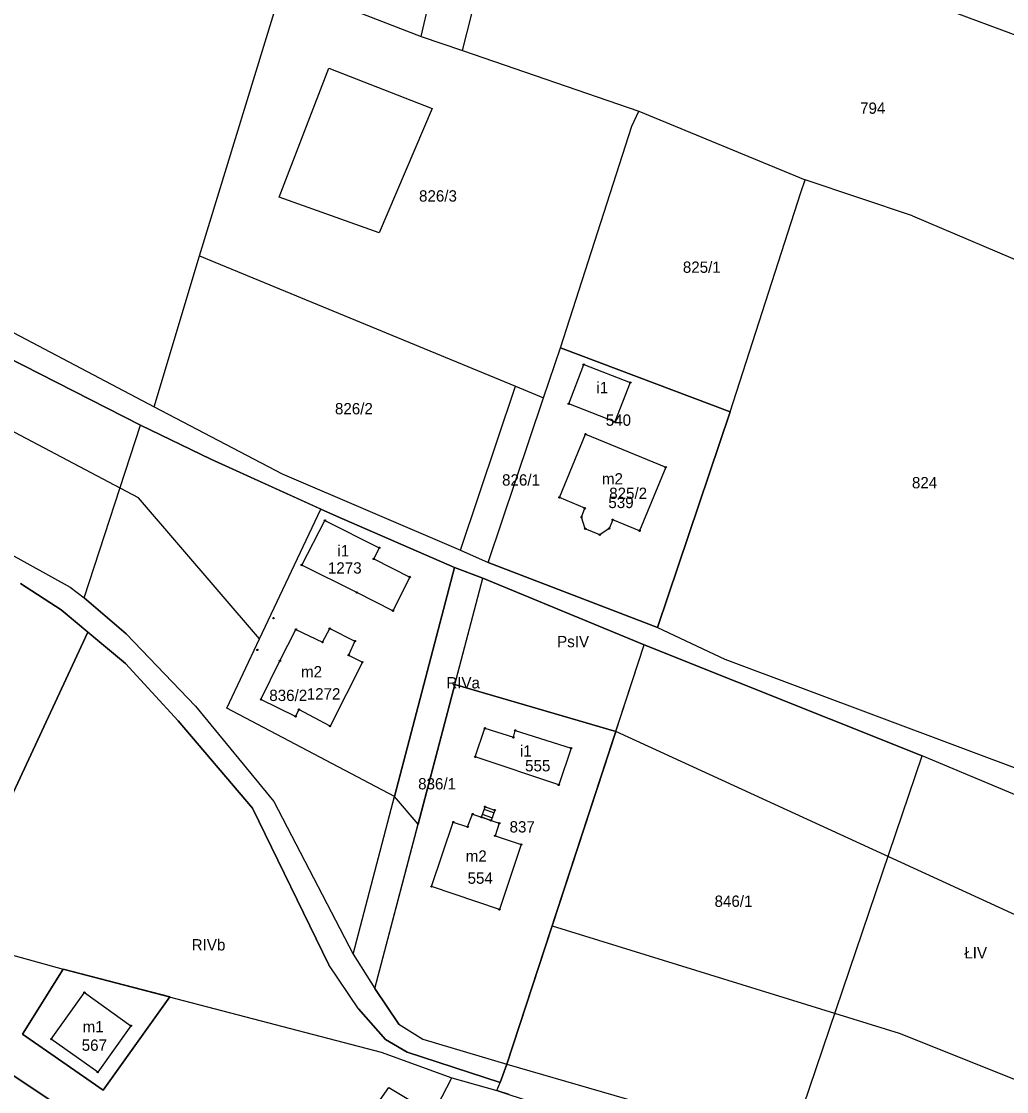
# Model space of a CAD drawing. Extents: x 7498273 to 7499989, y 5499795 to 5500810.
# Drawn here: x 7499281.1 to 7499411.6, y 5500351 to 5500492.7 of the extents above; entities that cross this region are included whole.
import ezdxf

# ---------------------------------------------------------------- set-up
doc = ezdxf.new("R2010")
doc.units = 0
for name, color, linetype in [('209-oznaczenie konturu klasyfikacyjnego', 7, 'Continuous'), ('211-numer działki ewidencyjnej', 7, 'Continuous'), ('217-kontur klasyfikacyjny', 7, 'Continuous'), ('218-kontur użytku gruntowego', 7, 'Continuous'), ('219-działka ewidencyjna', 7, 'Continuous'), ('312-budynek ewidencyjny', 7, 'Continuous'), ('312-oznaczenie budynku ewidencyjnego', 7, 'Continuous'), ('312-oznaczenie budynku ewidencyjnego-Atr117', 7, 'Continuous'), ('352-schody', 7, 'Continuous'), ('Punkt budynku', 7, 'Continuous')]:
    doc.layers.add(name, color=color, linetype=linetype)

# ---------------------------------------------------------------- blocks, each defined once
blk = doc.blocks.new('PUNKTBUD')
blk.add_circle((0, 0), 0.09)

msp = doc.modelspace()

# ---------------------------------------------------------------- linework, layer by layer
at = {"layer": '217-kontur klasyfikacyjny'}
for points in [[(7499296.61, 5500429.63), (7499178.7, 5500491.9)], [(7499315.23, 5500469.46), (7499321.8, 5500486.55)], [(7499321.8, 5500486.55), (7499335.49, 5500481.22)], [(7499335.49, 5500481.22), (7499328.47, 5500464.71)], [(7499328.47, 5500464.71), (7499315.23, 5500469.46)], [(7499254.08, 5500465.15), (7499298.69, 5500441.68)], [(7499219.39, 5500455.52), (7499287.55, 5500417.77)], [(7499296.87, 5500439.23), (7499270.17, 5500452.83)], [(7499350.27, 5500442.88), (7499352.51, 5500449.51)], [(7499352.51, 5500449.51), (7499374.97, 5500441.03)], [(7499342.94, 5500421.06), (7499350.27, 5500442.88)], [(7499298.69, 5500441.68), (7499315.65, 5500432.8)], [(7499374.97, 5500441.03), (7499365.34, 5500412.42)], [(7499306.2, 5500434.76), (7499296.87, 5500439.23)], [(7499320.75, 5500428.13), (7499306.2, 5500434.76)], [(7499315.65, 5500432.8), (7499339.26, 5500422.68)], [(7499312.63, 5500410.92), (7499296.61, 5500429.63)], [(7499312.63, 5500410.92), (7499320.75, 5500428.13)], [(7499320.75, 5500428.13), (7499322.82, 5500427.19)], [(7499322.82, 5500427.19), (7499338.47, 5500420.37)], [(7499339.26, 5500422.68), (7499342.94, 5500421.06)], [(7499338.47, 5500420.37), (7499330.52, 5500390.03)], [(7499342.23, 5500418.97), (7499338.47, 5500420.37)], [(7499365.34, 5500412.42), (7499342.94, 5500421.06)], [(7499338.53, 5500404.91), (7499342.23, 5500418.97)], [(7499363.59, 5500410.14), (7499342.23, 5500418.97)], [(7499286.37, 5500414.76), (7499280.96, 5500418.29)], [(7499287.55, 5500417.77), (7499289.39, 5500416.38)], [(7499289.39, 5500416.38), (7499294.97, 5500411.6)], [(7499289.91, 5500411.82), (7499286.37, 5500414.76)], [(7499277.96, 5500386.26), (7499289.91, 5500411.82)], [(7499294.88, 5500407.68), (7499289.91, 5500411.82)], [(7499294.97, 5500411.6), (7499304.17, 5500402.04)], [(7499365.34, 5500412.42), (7499374.26, 5500408.23)], [(7499308.3, 5500401.74), (7499312.63, 5500410.92)], [(7499359.84, 5500398.68), (7499363.59, 5500410.14)], [(7499400.41, 5500395.43), (7499363.59, 5500410.14)], [(7499301.84, 5500400.08), (7499294.88, 5500407.68)], [(7499374.26, 5500408.23), (7499415.1, 5500392.98)], [(7499333.66, 5500386.37), (7499338.53, 5500404.91)], [(7499338.53, 5500404.91), (7499359.84, 5500398.68)], [(7499304.17, 5500402.04), (7499314.54, 5500389.39)], [(7499330.52, 5500390.03), (7499308.3, 5500401.74)], [(7499311.71, 5500388.52), (7499301.84, 5500400.08)], [(7499359.84, 5500398.68), (7499351.41, 5500372.91)], [(7499417.66, 5500372.13), (7499359.84, 5500398.68)], [(7499414.64, 5500389.48), (7499400.41, 5500395.43)], [(7499314.54, 5500389.39), (7499325.06, 5500369.17)], [(7499333.66, 5500386.37), (7499330.52, 5500390.03)], [(7499321.84, 5500367.74), (7499311.71, 5500388.52)], [(7499327.93, 5500364.61), (7499333.66, 5500386.37)], [(7499351.41, 5500372.91), (7499345.42, 5500354.59)], [(7499351.41, 5500372.91), (7499397.37, 5500358.71)], [(7499325.06, 5500369.17), (7499327.93, 5500364.61)], [(7499325.73, 5500361.93), (7499321.84, 5500367.74)], [(7499259.58, 5500366.67), (7499295.09, 5500343.03)], [(7499281.22, 5500358.58), (7499286.62, 5500367.17)], [(7499286.62, 5500367.17), (7499300.74, 5500363.49)], [(7499300.74, 5500363.49), (7499291.91, 5500351.13)], [(7499329.32, 5500357.84), (7499325.73, 5500361.93)], [(7499291.91, 5500351.13), (7499281.22, 5500358.58)], [(7499332.19, 5500356.19), (7499329.32, 5500357.84)], [(7499397.37, 5500358.71), (7499452.93, 5500336.49)], [(7499344.53, 5500352.15), (7499332.19, 5500356.19)], [(7499345.42, 5500354.59), (7499344.53, 5500352.15)], [(7499344.06, 5500351.09), (7499344.53, 5500352.15)], [(7499321.5, 5500339.77), (7499329.78, 5500351.5)], [(7499329.78, 5500351.5), (7499335.63, 5500347.98)], [(7499345.71, 5500350.55), (7499344.06, 5500351.09)]]:
    msp.add_lwpolyline(points, dxfattribs=at)
at = {"layer": '218-kontur użytku gruntowego'}
for points in [[(7499296.61, 5500429.63), (7499178.7, 5500491.9)], [(7499315.23, 5500469.46), (7499321.8, 5500486.55)], [(7499321.8, 5500486.55), (7499335.49, 5500481.22)], [(7499335.49, 5500481.22), (7499328.47, 5500464.71)], [(7499328.47, 5500464.71), (7499315.23, 5500469.46)], [(7499254.08, 5500465.15), (7499298.69, 5500441.68)], [(7499219.39, 5500455.52), (7499287.55, 5500417.77)], [(7499296.87, 5500439.23), (7499270.17, 5500452.83)], [(7499350.27, 5500442.88), (7499352.51, 5500449.51)], [(7499352.51, 5500449.51), (7499374.97, 5500441.03)], [(7499342.94, 5500421.06), (7499350.27, 5500442.88)], [(7499298.69, 5500441.68), (7499315.65, 5500432.8)], [(7499374.97, 5500441.03), (7499365.34, 5500412.42)], [(7499306.2, 5500434.76), (7499296.87, 5500439.23)], [(7499320.75, 5500428.13), (7499306.2, 5500434.76)], [(7499315.65, 5500432.8), (7499339.26, 5500422.68)], [(7499312.63, 5500410.92), (7499296.61, 5500429.63)], [(7499312.63, 5500410.92), (7499320.75, 5500428.13)], [(7499322.82, 5500427.19), (7499320.75, 5500428.13)], [(7499338.47, 5500420.37), (7499322.82, 5500427.19)], [(7499339.26, 5500422.68), (7499342.94, 5500421.06)], [(7499330.52, 5500390.03), (7499338.47, 5500420.37)], [(7499342.23, 5500418.97), (7499338.47, 5500420.37)], [(7499342.94, 5500421.06), (7499365.34, 5500412.42)], [(7499338.53, 5500404.91), (7499342.23, 5500418.97)], [(7499363.59, 5500410.14), (7499342.23, 5500418.97)], [(7499286.37, 5500414.76), (7499280.96, 5500418.29)], [(7499287.55, 5500417.77), (7499289.39, 5500416.38)], [(7499289.39, 5500416.38), (7499294.97, 5500411.6)], [(7499289.91, 5500411.82), (7499286.37, 5500414.76)], [(7499289.91, 5500411.82), (7499277.96, 5500386.26)], [(7499294.88, 5500407.68), (7499289.91, 5500411.82)], [(7499294.97, 5500411.6), (7499304.17, 5500402.04)], [(7499365.34, 5500412.42), (7499374.26, 5500408.23)], [(7499308.3, 5500401.74), (7499312.63, 5500410.92)], [(7499359.84, 5500398.68), (7499363.59, 5500410.14)], [(7499400.41, 5500395.43), (7499363.59, 5500410.14)], [(7499301.84, 5500400.08), (7499294.88, 5500407.68)], [(7499374.26, 5500408.23), (7499415.1, 5500392.98)], [(7499338.53, 5500404.91), (7499333.66, 5500386.37)], [(7499359.84, 5500398.68), (7499338.53, 5500404.91)], [(7499304.17, 5500402.04), (7499314.54, 5500389.39)], [(7499330.52, 5500390.03), (7499308.3, 5500401.74)], [(7499311.71, 5500388.52), (7499301.84, 5500400.08)], [(7499351.41, 5500372.91), (7499359.84, 5500398.68)], [(7499417.66, 5500372.13), (7499359.84, 5500398.68)], [(7499414.64, 5500389.48), (7499400.41, 5500395.43)], [(7499314.54, 5500389.39), (7499325.06, 5500369.17)], [(7499333.66, 5500386.37), (7499330.52, 5500390.03)], [(7499321.84, 5500367.74), (7499311.71, 5500388.52)], [(7499327.93, 5500364.61), (7499333.66, 5500386.37)], [(7499345.42, 5500354.59), (7499351.41, 5500372.91)], [(7499351.41, 5500372.91), (7499397.37, 5500358.71)], [(7499325.06, 5500369.17), (7499327.93, 5500364.61)], [(7499325.73, 5500361.93), (7499321.84, 5500367.74)], [(7499259.58, 5500366.67), (7499295.09, 5500343.03)], [(7499286.62, 5500367.17), (7499281.22, 5500358.58)], [(7499300.74, 5500363.49), (7499286.62, 5500367.17)], [(7499291.91, 5500351.13), (7499300.74, 5500363.49)], [(7499327.93, 5500364.61), (7499331.09, 5500359.88)], [(7499329.32, 5500357.84), (7499325.73, 5500361.93)], [(7499331.09, 5500359.88), (7499334.28, 5500357.9)], [(7499281.22, 5500358.58), (7499291.91, 5500351.13)], [(7499332.19, 5500356.19), (7499329.32, 5500357.84)], [(7499334.28, 5500357.9), (7499345.42, 5500354.59)], [(7499397.37, 5500358.71), (7499452.93, 5500336.49)], [(7499344.53, 5500352.15), (7499332.19, 5500356.19)], [(7499345.42, 5500354.59), (7499344.53, 5500352.15)], [(7499344.06, 5500351.09), (7499344.53, 5500352.15)], [(7499321.5, 5500339.77), (7499329.78, 5500351.5)], [(7499329.78, 5500351.5), (7499335.63, 5500347.98)], [(7499345.71, 5500350.55), (7499344.06, 5500351.09)]]:
    msp.add_lwpolyline(points, dxfattribs=at)
at = {"layer": '219-działka ewidencyjna'}
for points in [[(7499339.53, 5500488.89), (7499346.34, 5500515.65)], [(7499346.34, 5500515.65), (7499444.86, 5500479.04)], [(7499334.06, 5500490.73), (7499339.55, 5500514.64)], [(7499304.67, 5500461.68), (7499315.76, 5500497.85)], [(7499315.76, 5500497.85), (7499334.06, 5500490.73)], [(7499334.06, 5500490.73), (7499339.53, 5500488.89)], [(7499339.53, 5500488.89), (7499362.87, 5500480.83)], [(7499361.95, 5500478.87), (7499362.87, 5500480.83)], [(7499362.87, 5500480.83), (7499384.93, 5500471.77)], [(7499352.51, 5500449.51), (7499361.95, 5500478.87)], [(7499384.36, 5500470.07), (7499384.93, 5500471.77)], [(7499399.15, 5500466.97), (7499384.93, 5500471.77)], [(7499374.97, 5500441.03), (7499384.36, 5500470.07)], [(7499399.15, 5500466.97), (7499432.79, 5500452.67)], [(7499254.08, 5500465.15), (7499298.69, 5500441.68)], [(7499298.69, 5500441.68), (7499304.67, 5500461.68)], [(7499304.67, 5500461.68), (7499346.56, 5500444.42)], [(7499219.39, 5500455.52), (7499287.55, 5500417.77)], [(7499270.17, 5500452.83), (7499296.87, 5500439.23)], [(7499350.27, 5500442.88), (7499352.51, 5500449.51)], [(7499374.97, 5500441.03), (7499352.51, 5500449.51)], [(7499339.26, 5500422.68), (7499346.56, 5500444.42)], [(7499346.56, 5500444.42), (7499350.27, 5500442.88)], [(7499342.94, 5500421.06), (7499350.27, 5500442.88)], [(7499298.69, 5500441.68), (7499315.65, 5500432.8)], [(7499365.34, 5500412.42), (7499374.97, 5500441.03)], [(7499289.39, 5500416.38), (7499296.87, 5500439.23)], [(7499296.87, 5500439.23), (7499306.2, 5500434.76)], [(7499306.2, 5500434.76), (7499322.82, 5500427.19)], [(7499315.65, 5500432.8), (7499339.26, 5500422.68)], [(7499322.82, 5500427.19), (7499338.47, 5500420.37)], [(7499339.26, 5500422.68), (7499342.94, 5500421.06)], [(7499325.06, 5500369.17), (7499338.47, 5500420.37)], [(7499338.47, 5500420.37), (7499342.23, 5500418.97)], [(7499365.34, 5500412.42), (7499342.94, 5500421.06)], [(7499327.93, 5500364.61), (7499342.23, 5500418.97)], [(7499342.23, 5500418.97), (7499363.59, 5500410.14)], [(7499280.96, 5500418.29), (7499286.37, 5500414.76)], [(7499287.55, 5500417.77), (7499289.39, 5500416.38)], [(7499294.97, 5500411.6), (7499289.39, 5500416.38)], [(7499286.37, 5500414.76), (7499294.88, 5500407.68)], [(7499294.97, 5500411.6), (7499304.17, 5500402.04)], [(7499365.34, 5500412.42), (7499374.26, 5500408.23)], [(7499345.42, 5500354.59), (7499363.59, 5500410.14)], [(7499363.59, 5500410.14), (7499400.41, 5500395.43)], [(7499294.88, 5500407.68), (7499301.84, 5500400.08)], [(7499374.26, 5500408.23), (7499415.1, 5500392.98)], [(7499304.17, 5500402.04), (7499314.54, 5500389.39)], [(7499301.84, 5500400.08), (7499311.71, 5500388.52)], [(7499382.89, 5500343.71), (7499400.41, 5500395.43)], [(7499414.64, 5500389.48), (7499400.41, 5500395.43)], [(7499314.54, 5500389.39), (7499325.06, 5500369.17)], [(7499311.71, 5500388.52), (7499321.84, 5500367.74)], [(7499271.48, 5500371.36), (7499286.62, 5500367.17)], [(7499325.06, 5500369.17), (7499327.93, 5500364.61)], [(7499325.73, 5500361.93), (7499321.84, 5500367.74)], [(7499295.09, 5500343.03), (7499259.58, 5500366.67)], [(7499286.62, 5500367.17), (7499328.73, 5500356.2)], [(7499331.09, 5500359.88), (7499327.93, 5500364.61)], [(7499325.73, 5500361.93), (7499329.32, 5500357.84)], [(7499331.09, 5500359.88), (7499334.28, 5500357.9)], [(7499329.32, 5500357.84), (7499332.19, 5500356.19)], [(7499334.28, 5500357.9), (7499345.42, 5500354.59)], [(7499328.73, 5500356.2), (7499338.12, 5500352.79)], [(7499332.19, 5500356.19), (7499344.53, 5500352.15)], [(7499344.53, 5500352.15), (7499345.42, 5500354.59)], [(7499345.42, 5500354.59), (7499382.89, 5500343.71)], [(7499322.7, 5500323), (7499338.12, 5500352.79)], [(7499338.12, 5500352.79), (7499344.06, 5500351.09)], [(7499344.06, 5500351.09), (7499344.53, 5500352.15)], [(7499344.06, 5500351.09), (7499358.4, 5500346.36)]]:
    msp.add_lwpolyline(points, dxfattribs=at)
at = {"layer": '312-budynek ewidencyjny'}
for points in [[(7499353.6, 5500442.08), (7499355.58, 5500447.28)], [(7499355.58, 5500447.28), (7499361.76, 5500444.89)], [(7499361.76, 5500444.89), (7499359.73, 5500439.67)], [(7499359.73, 5500439.67), (7499353.6, 5500442.08)], [(7499352.37, 5500429.68), (7499355.82, 5500438.07)], [(7499355.82, 5500438.07), (7499366.45, 5500433.68)], [(7499366.45, 5500433.68), (7499362.98, 5500425.27)], [(7499355.73, 5500428.23), (7499352.37, 5500429.68)], [(7499355.29, 5500427.08), (7499355.73, 5500428.23)], [(7499318.23, 5500420.72), (7499321.3, 5500426.63)], [(7499321.3, 5500426.63), (7499328.5, 5500423.01)], [(7499355.79, 5500425.52), (7499355.29, 5500427.08)], [(7499359.43, 5500426.72), (7499358.95, 5500425.54)], [(7499362.98, 5500425.27), (7499359.43, 5500426.72)], [(7499357.72, 5500424.71), (7499355.79, 5500425.52)], [(7499358.95, 5500425.54), (7499357.72, 5500424.71)], [(7499328.5, 5500423.01), (7499327.76, 5500421.52)], [(7499327.76, 5500421.52), (7499332.54, 5500419.13)], [(7499325.53, 5500417.07), (7499318.23, 5500420.72)], [(7499332.54, 5500419.13), (7499330.31, 5500414.67)], [(7499330.31, 5500414.67), (7499325.53, 5500417.07)], [(7499315.33, 5500408.03), (7499317.45, 5500412.18)], [(7499317.45, 5500412.18), (7499320.98, 5500410.49)], [(7499320.98, 5500410.49), (7499321.94, 5500412.29)], [(7499321.94, 5500412.29), (7499325.28, 5500410.65)], [(7499325.28, 5500410.65), (7499324.44, 5500408.78)], [(7499324.44, 5500408.78), (7499326.26, 5500407.85)], [(7499312.83, 5500402.9), (7499315.33, 5500408.03)], [(7499326.26, 5500407.85), (7499321.98, 5500399.37)], [(7499317.41, 5500400.67), (7499312.83, 5500402.9)], [(7499317.85, 5500401.56), (7499317.41, 5500400.67)], [(7499321.98, 5500399.37), (7499317.85, 5500401.56)], [(7499341.21, 5500395.29), (7499342.49, 5500399.1)], [(7499342.49, 5500399.1), (7499346.27, 5500397.89)], [(7499346.27, 5500397.89), (7499346.51, 5500398.8)], [(7499346.51, 5500398.8), (7499353.91, 5500396.47)], [(7499353.91, 5500396.47), (7499352.27, 5500391.58)], [(7499352.27, 5500391.58), (7499341.21, 5500395.29)], [(7499340.21, 5500386.05), (7499340.87, 5500387.72)], [(7499340.87, 5500387.72), (7499342.04, 5500387.32)], [(7499335.42, 5500378.14), (7499338.3, 5500386.67)], [(7499338.3, 5500386.67), (7499340.21, 5500386.05)], [(7499342.04, 5500387.32), (7499343.32, 5500386.88)], [(7499343.32, 5500386.88), (7499344.39, 5500386.51)], [(7499344.39, 5500386.51), (7499343.84, 5500384.84)], [(7499343.84, 5500384.84), (7499347.32, 5500383.69)], [(7499347.32, 5500383.69), (7499344.42, 5500375.1)], [(7499344.42, 5500375.1), (7499335.42, 5500378.14)], [(7499285.04, 5500357.9), (7499289.44, 5500364.07)], [(7499289.44, 5500364.07), (7499295.59, 5500359.68)], [(7499295.59, 5500359.68), (7499291.21, 5500353.53)], [(7499291.21, 5500353.53), (7499285.04, 5500357.9)]]:
    msp.add_lwpolyline(points, dxfattribs=at)
at = {"layer": '352-schody'}
msp.add_lwpolyline([(7499342.04, 5500387.32), (7499342.52, 5500388.7), (7499343.8, 5500388.26), (7499343.32, 5500386.88)], close=True, dxfattribs=at)
msp.add_lwpolyline([(7499342.04, 5500387.32), (7499342.52, 5500388.7), (7499343.8, 5500388.26), (7499343.32, 5500386.88)], close=True, dxfattribs=at)
for points in [[(7499343.433, 5500387.206), (7499342.155, 5500387.651)], [(7499343.663, 5500387.867), (7499342.385, 5500388.312)]]:
    msp.add_lwpolyline(points, dxfattribs=at)

# ---------------------------------------------------------------- block references
at = {"layer": 'Punkt budynku'}
for p in [(7499355.58, 5500447.28), (7499361.76, 5500444.89), (7499353.6, 5500442.08), (7499359.73, 5500439.67), (7499355.82, 5500438.07), (7499366.45, 5500433.68), (7499352.37, 5500429.68), (7499355.29, 5500427.08), (7499355.73, 5500428.23), (7499321.3, 5500426.63), (7499359.43, 5500426.72), (7499355.79, 5500425.52), (7499357.72, 5500424.71), (7499358.95, 5500425.54), (7499362.98, 5500425.27), (7499328.5, 5500423.01), (7499327.76, 5500421.52), (7499318.23, 5500420.72), (7499332.54, 5500419.13), (7499325.53, 5500417.07), (7499330.31, 5500414.67), (7499314.49, 5500413.69), (7499317.45, 5500412.18), (7499321.94, 5500412.29), (7499320.98, 5500410.49), (7499325.28, 5500410.65), (7499312.36, 5500409.47), (7499324.44, 5500408.78), (7499315.33, 5500408.03), (7499326.26, 5500407.85), (7499312.83, 5500402.9), (7499317.85, 5500401.56), (7499317.41, 5500400.67), (7499321.98, 5500399.37), (7499342.49, 5500399.1), (7499346.51, 5500398.8), (7499346.27, 5500397.89), (7499353.91, 5500396.47), (7499341.21, 5500395.29), (7499352.27, 5500391.58), (7499340.87, 5500387.72), (7499342.52, 5500388.7), (7499343.8, 5500388.26), (7499338.3, 5500386.67), (7499340.21, 5500386.05), (7499342.04, 5500387.32), (7499343.32, 5500386.88), (7499344.39, 5500386.51), (7499343.84, 5500384.84), (7499347.32, 5500383.69), (7499335.42, 5500378.14), (7499344.42, 5500375.1), (7499289.44, 5500364.07), (7499295.59, 5500359.68), (7499285.04, 5500357.9), (7499291.21, 5500353.53)]:
    msp.add_blockref('PUNKTBUD', p, dxfattribs=at)

# ---------------------------------------------------------------- texts
at = {"layer": '209-oznaczenie konturu klasyfikacyjnego'}
for s, p in [('PsIV', (7499352.06, 5500409.83)), ('RIVa', (7499337.38, 5500404.37)), ('RIVb', (7499303.65, 5500369.65)), ('ŁIV', (7499406.01, 5500368.59))]:
    msp.add_text(s, height=1.5, dxfattribs=at).set_placement(p)
at = {"layer": '211-numer działki ewidencyjnej'}
for s, p in [('794', (7499392.2, 5500480.5)), ('826/3', (7499333.77, 5500468.87)), ('825/1', (7499368.72, 5500459.43)), ('826/2', (7499322.63, 5500440.68)), ('826/1', (7499344.77, 5500431.24)), ('824', (7499399.07, 5500430.88)), ('825/2', (7499358.96, 5500429.47)), ('836/2', (7499313.93, 5500402.7)), ('836/1', (7499333.65, 5500390.99)), ('837', (7499345.76, 5500385.28)), ('846/1', (7499372.92, 5500375.43))]:
    msp.add_text(s, height=1.5, dxfattribs=at).set_placement(p)
at = {"layer": '312-oznaczenie budynku ewidencyjnego'}
for s, p in [('540', (7499358.51, 5500439.17)), ('539', (7499358.85, 5500428.26)), ('1273', (7499321.7, 5500419.58)), ('1272', (7499318.89, 5500402.9)), ('555', (7499347.82, 5500393.38)), ('554', (7499340.2, 5500378.49)), ('567', (7499289.08, 5500356.36))]:
    msp.add_text(s, height=1.5, dxfattribs=at).set_placement(p)
at = {"layer": '312-oznaczenie budynku ewidencyjnego-Atr117'}
for s, p in [('i1', (7499357.262, 5500443.48)), ('m2', (7499357.996, 5500431.39)), ('i1', (7499322.952, 5500421.85)), ('m2', (7499318.136, 5500405.83)), ('i1', (7499347.142, 5500395.34)), ('m2', (7499339.956, 5500381.41)), ('m1', (7499289.195, 5500358.8))]:
    msp.add_text(s, height=1.5, dxfattribs=at).set_placement(p)

doc.saveas('drawing.dxf')
